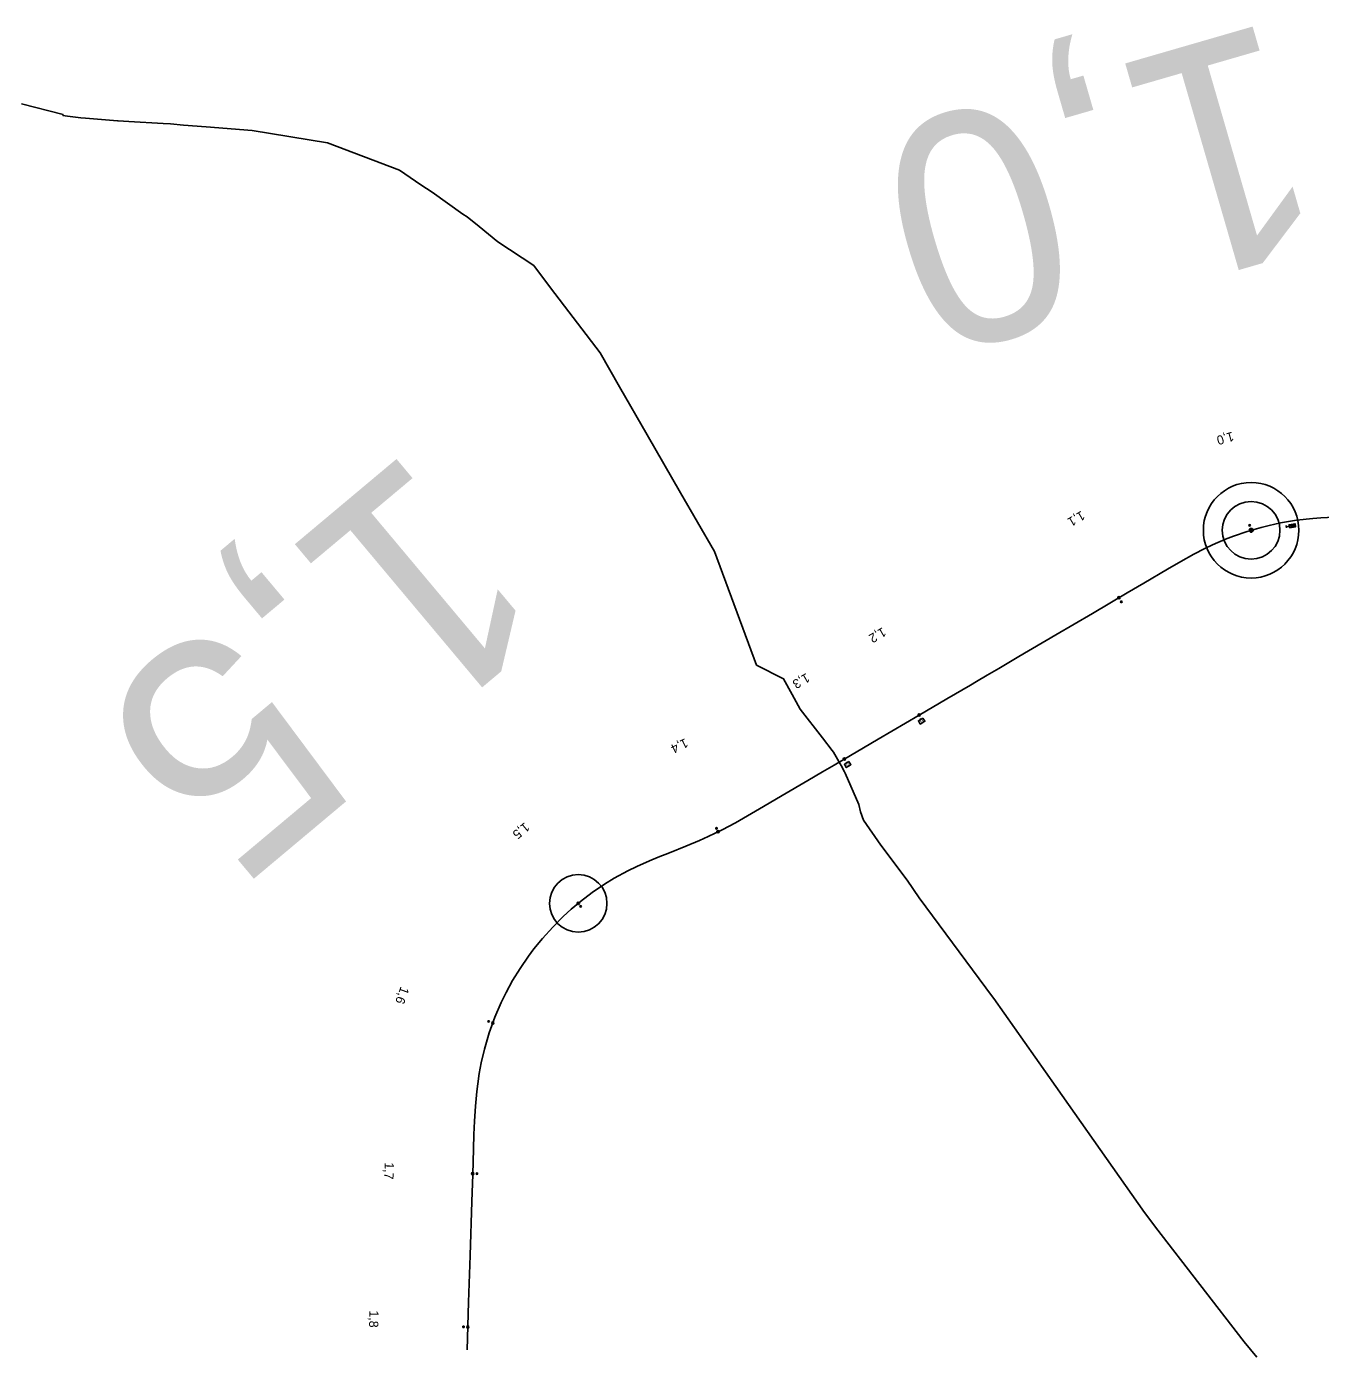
# Model space of a CAD drawing. Extents: x -738519 to -733269, y -1123734 to -1116309.
# Drawn here: x -735766 to -734923, y -1120704 to -1119839 of the extents above; entities that cross this region are included whole.
import ezdxf

# ---------------------------------------------------------------- set-up
doc = ezdxf.new("R2010")
doc.units = 0
for name, color, linetype in [('DKM', 7, 'Continuous'), ('Vrstva 1', 7, 'Continuous'), ('Vrstva 13', 7, 'Continuous'), ('Vrstva 7', 7, 'Continuous')]:
    doc.layers.add(name, color=color, linetype=linetype)

msp = doc.modelspace()

# ---------------------------------------------------------------- linework, layer by layer
at = {"layer": 'DKM'}
msp.add_lwpolyline([(-734964.14, -1120706.24), (-734972.36, -1120696.27), (-735030.04, -1120621.33), (-735033.19, -1120617.24), (-735037.29, -1120611.91), (-735095.05, -1120529.74), (-735135.53, -1120472.38), (-735136.45, -1120471.14), (-735184.26, -1120406.79), (-735192.01, -1120395.09), (-735209.2, -1120372.29), (-735220.41, -1120355.94), (-735222.54, -1120350.71), (-735223.57, -1120345.84), (-735232.39, -1120325.34), (-735232.79, -1120324.54), (-735235.15, -1120320.33), (-735236.32, -1120318.24), (-735237.48, -1120316.17), (-735240.01, -1120311.65), (-735240.86, -1120310.61), (-735247.23, -1120302.41), (-735261.74, -1120283.75), (-735267.06, -1120274.13), (-735272.61, -1120263.87), (-735290.18, -1120254.92), (-735317.57, -1120180.85), (-735339.79, -1120142.5), (-735361.49, -1120104.8), (-735379.62, -1120073.45), (-735392.28, -1120051.31), (-735424.51, -1120008.85), (-735435.47, -1119994.41), (-735458.88, -1119978.9), (-735471.18, -1119968.88), (-735478.93, -1119962.57), (-735481.75, -1119960.82), (-735501.85, -1119946.58), (-735509.06, -1119941.71), (-735523.05, -1119932.09), (-735569.89, -1119914.41), (-735619.21, -1119906.36), (-735649, -1119903.96), (-735663.95, -1119902.76), (-735672.41, -1119902.07), (-735677.05, -1119901.7), (-735699.55, -1119900.4), (-735706.55, -1119900), (-735706.86, -1119899.98), (-735727.79, -1119898.29), (-735730.81, -1119898.05), (-735739.44, -1119896.94), (-735742.5, -1119896.54), (-735742.38, -1119895.95), (-735769.61, -1119889.03)], dxfattribs=at)
at = {"layer": 'Vrstva 1'}
for points in [[(-734858.48, -1120165.34), (-734868.3, -1120163.18), (-734878.26, -1120161.29), (-734888.48, -1120159.82), (-734893.81, -1120159.29), (-734903.72, -1120158.67), (-734913.62, -1120158.56), (-734922.39, -1120158.89), (-734927.49, -1120159.26), (-734938.14, -1120160.47), (-734948.63, -1120162.22), (-734955.93, -1120163.8), (-734961.26, -1120165.13), (-734970.23, -1120167.73), (-734979.17, -1120170.78), (-734984.57, -1120172.85), (-734992.91, -1120176.44), (-734998.02, -1120178.89), (-735005.2, -1120182.65), (-735013.61, -1120187.35), (-735022.2, -1120192.38), (-735037.65, -1120201.44), (-735048.63, -1120207.9)], [(-734858.48, -1120165.34), (-734868.3, -1120163.18), (-734878.26, -1120161.29), (-734888.48, -1120159.82), (-734893.81, -1120159.29), (-734903.72, -1120158.67), (-734913.62, -1120158.56), (-734922.39, -1120158.89), (-734927.49, -1120159.26), (-734938.14, -1120160.47), (-734948.63, -1120162.22), (-734955.93, -1120163.8), (-734961.26, -1120165.13), (-734970.23, -1120167.73), (-734979.17, -1120170.78), (-734984.57, -1120172.85), (-734992.91, -1120176.44), (-734998.02, -1120178.89), (-735005.2, -1120182.65), (-735013.61, -1120187.35), (-735022.2, -1120192.38), (-735037.65, -1120201.44), (-735048.63, -1120207.9)], [(-735048.63, -1120207.9), (-735071.26, -1120221.19), (-735095.02, -1120235.15), (-735119.18, -1120249.35), (-735123.66, -1120251.99), (-735132.32, -1120257.08), (-735139.95, -1120261.55), (-735146.73, -1120265.54), (-735150.83, -1120267.95), (-735166.13, -1120276.92), (-735184.2, -1120287.53), (-735210.89, -1120303.2), (-735238.62, -1120319.49), (-735239.7, -1120320.12), (-735247.26, -1120324.55), (-735256.8, -1120330.14), (-735273.62, -1120340.02), (-735285.77, -1120347.18), (-735296.08, -1120353.22), (-735304.06, -1120357.75)], [(-735048.63, -1120207.9), (-735071.26, -1120221.19), (-735095.02, -1120235.15), (-735119.18, -1120249.35), (-735123.66, -1120251.99), (-735132.32, -1120257.08), (-735139.95, -1120261.55), (-735146.73, -1120265.54), (-735150.83, -1120267.95), (-735166.13, -1120276.92), (-735184.2, -1120287.53), (-735210.89, -1120303.2), (-735238.62, -1120319.49), (-735239.7, -1120320.12), (-735247.26, -1120324.55), (-735256.8, -1120330.14), (-735273.62, -1120340.02), (-735285.77, -1120347.18), (-735296.08, -1120353.22), (-735304.06, -1120357.75)], [(-735304.06, -1120357.75), (-735312.6, -1120362.28), (-735321.76, -1120366.74), (-735327.51, -1120369.32), (-735336.44, -1120373.09), (-735346.98, -1120377.26), (-735354.33, -1120380.21), (-735360.07, -1120382.6), (-735368.33, -1120386.31), (-735374.16, -1120389.16), (-735382.98, -1120393.95), (-735389.27, -1120397.76), (-735397.43, -1120403.28), (-735404.93, -1120408.97), (-735411.01, -1120414.07), (-735416.27, -1120418.85), (-735423.16, -1120425.73), (-735429.79, -1120433.1), (-735435.35, -1120439.92), (-735438.96, -1120444.69), (-735444.43, -1120452.73), (-735449.27, -1120460.68), (-735453.57, -1120468.51), (-735456.72, -1120474.99), (-735460.8, -1120484.48), (-735464.55, -1120494.8), (-735467.61, -1120505.27), (-735469.73, -1120514.19), (-735471.02, -1120521.28), (-735472.03, -1120528.02), (-735472.64, -1120533.02), (-735473.48, -1120542.45), (-735474.08, -1120552.34), (-735474.47, -1120561.09), (-735474.78, -1120570.26), (-735475.33, -1120587.19), (-735475.9, -1120604.74)], [(-735304.06, -1120357.75), (-735312.6, -1120362.28), (-735321.76, -1120366.74), (-735327.51, -1120369.32), (-735336.44, -1120373.09), (-735346.98, -1120377.26), (-735354.33, -1120380.21), (-735360.07, -1120382.6), (-735368.33, -1120386.31), (-735374.16, -1120389.16), (-735382.98, -1120393.95), (-735389.27, -1120397.76), (-735397.43, -1120403.28), (-735404.93, -1120408.97), (-735411.01, -1120414.07), (-735416.27, -1120418.85), (-735423.16, -1120425.73), (-735429.79, -1120433.1), (-735435.35, -1120439.92), (-735438.96, -1120444.69), (-735444.43, -1120452.73), (-735449.27, -1120460.68), (-735453.57, -1120468.51), (-735456.72, -1120474.99), (-735460.8, -1120484.48), (-735464.55, -1120494.8), (-735467.61, -1120505.27), (-735469.73, -1120514.19), (-735471.02, -1120521.28), (-735472.03, -1120528.02), (-735472.64, -1120533.02), (-735473.48, -1120542.45), (-735474.08, -1120552.34), (-735474.47, -1120561.09), (-735474.78, -1120570.26), (-735475.33, -1120587.19), (-735475.9, -1120604.74)], [(-735475.9, -1120604.74), (-735477.02, -1120639.86), (-735477.98, -1120670.26), (-735478.96, -1120701.34)], [(-735475.9, -1120604.74), (-735477.02, -1120639.86), (-735477.98, -1120670.26), (-735478.96, -1120701.34)]]:
    msp.add_lwpolyline(points, dxfattribs=at)
at = {"layer": 'Vrstva 13'}
for p, q in [((-735769.61, -1119889.03), (-735742.38, -1119895.95)), ((-735742.38, -1119895.95), (-735742.5, -1119896.54)), ((-735742.5, -1119896.54), (-735739.44, -1119896.94)), ((-735739.44, -1119896.94), (-735730.81, -1119898.05)), ((-735727.79, -1119898.29), (-735730.81, -1119898.05)), ((-735706.86, -1119899.98), (-735727.79, -1119898.29)), ((-735706.55, -1119900), (-735706.86, -1119899.98)), ((-735699.55, -1119900.4), (-735706.55, -1119900)), ((-735677.05, -1119901.7), (-735699.55, -1119900.4)), ((-735672.41, -1119902.07), (-735677.05, -1119901.7)), ((-735663.95, -1119902.76), (-735672.41, -1119902.07)), ((-735649, -1119903.96), (-735663.95, -1119902.76)), ((-735619.21, -1119906.36), (-735649, -1119903.96)), ((-735569.89, -1119914.41), (-735619.21, -1119906.36)), ((-735523.05, -1119932.09), (-735569.89, -1119914.41)), ((-735523.05, -1119932.09), (-735509.06, -1119941.71)), ((-735509.06, -1119941.71), (-735501.85, -1119946.58)), ((-735501.85, -1119946.58), (-735481.75, -1119960.82)), ((-735481.75, -1119960.82), (-735478.93, -1119962.57)), ((-735478.93, -1119962.57), (-735471.18, -1119968.88)), ((-735471.18, -1119968.88), (-735458.88, -1119978.9)), ((-735435.47, -1119994.41), (-735458.88, -1119978.9)), ((-735424.51, -1120008.85), (-735435.47, -1119994.41)), ((-735392.28, -1120051.31), (-735424.51, -1120008.85)), ((-735379.62, -1120073.45), (-735392.28, -1120051.31)), ((-735379.62, -1120073.45), (-735361.49, -1120104.8)), ((-735361.49, -1120104.8), (-735339.79, -1120142.5)), ((-735339.79, -1120142.5), (-735317.57, -1120180.85)), ((-735317.57, -1120180.85), (-735290.18, -1120254.92)), ((-735290.18, -1120254.92), (-735272.61, -1120263.87)), ((-735272.61, -1120263.87), (-735267.06, -1120274.13)), ((-735267.06, -1120274.13), (-735261.74, -1120283.75)), ((-735261.74, -1120283.75), (-735247.23, -1120302.41)), ((-735247.23, -1120302.41), (-735240.86, -1120310.61)), ((-735240.86, -1120310.61), (-735240.01, -1120311.65)), ((-735240.01, -1120311.65), (-735237.48, -1120316.17)), ((-735237.48, -1120316.17), (-735236.32, -1120318.24)), ((-735236.32, -1120318.24), (-735235.15, -1120320.33)), ((-735235.15, -1120320.33), (-735232.79, -1120324.54)), ((-735232.79, -1120324.54), (-735232.39, -1120325.34)), ((-735232.39, -1120325.34), (-735223.57, -1120345.84)), ((-735223.57, -1120345.84), (-735222.54, -1120350.71)), ((-735222.54, -1120350.71), (-735220.41, -1120355.94)), ((-735220.41, -1120355.94), (-735209.2, -1120372.29)), ((-735209.2, -1120372.29), (-735192.01, -1120395.09)), ((-735192.01, -1120395.09), (-735184.26, -1120406.79)), ((-735184.26, -1120406.79), (-735136.45, -1120471.14)), ((-735136.45, -1120471.14), (-735135.53, -1120472.38)), ((-735135.53, -1120472.38), (-735095.05, -1120529.74)), ((-735095.05, -1120529.74), (-735037.29, -1120611.91)), ((-735037.29, -1120611.91), (-735033.19, -1120617.24)), ((-735033.19, -1120617.24), (-735030.04, -1120621.33)), ((-735030.04, -1120621.33), (-734972.36, -1120696.27)), ((-734972.36, -1120696.27), (-734964.14, -1120706.24))]:
    msp.add_line(p, q, dxfattribs=at)
at = {"layer": 'Vrstva 7'}
for p, q in [((-734968.65, -1120163.77), (-734968.74, -1120163.8)), ((-734968.65, -1120163.77), (-734968.74, -1120163.8)), ((-734944.99, -1120163.95), (-734944.74, -1120165.43)), ((-734944.99, -1120163.95), (-734944.74, -1120165.43)), ((-734942.57, -1120163.29), (-734941.25, -1120165.1)), ((-734942.57, -1120163.29), (-734941.25, -1120165.1)), ((-734940.26, -1120164.93), (-734941.58, -1120163.12)), ((-734940.26, -1120164.93), (-734941.58, -1120163.12)), ((-734940.59, -1120162.96), (-734939.28, -1120164.77)), ((-734940.59, -1120162.96), (-734939.28, -1120164.77)), ((-735052.31, -1120213.67), (-735052.4, -1120213.72)), ((-735052.31, -1120213.67), (-735052.4, -1120213.72)), ((-735183.52, -1120289.79), (-735183.21, -1120290.33)), ((-735183.52, -1120289.79), (-735183.21, -1120290.33)), ((-735231.79, -1120318.14), (-735231.47, -1120318.68)), ((-735231.79, -1120318.14), (-735231.47, -1120318.68)), ((-735316.31, -1120361.39), (-735316.4, -1120361.43)), ((-735316.31, -1120361.39), (-735316.4, -1120361.43)), ((-735404.86, -1120412.19), (-735404.94, -1120412.26)), ((-735404.86, -1120412.19), (-735404.94, -1120412.26)), ((-735464.95, -1120487.25), (-735464.98, -1120487.34)), ((-735464.95, -1120487.25), (-735464.98, -1120487.34)), ((-735472.51, -1120586.52), (-735472.52, -1120586.62)), ((-735472.51, -1120586.52), (-735472.52, -1120586.62)), ((-735481.32, -1120686.38), (-735481.33, -1120686.48)), ((-735481.32, -1120686.38), (-735481.33, -1120686.48))]:
    msp.add_line(p, q, dxfattribs=at)
msp.add_lwpolyline([(-734944.87, -1120164.69), (-734942.9, -1120164.36), (-734942.73, -1120165.34), (-734938.79, -1120164.68), (-734939.12, -1120162.71), (-734943.06, -1120163.37), (-734942.9, -1120164.36)], dxfattribs=at)
msp.add_lwpolyline([(-734944.87, -1120164.69), (-734942.9, -1120164.36), (-734942.73, -1120165.34), (-734938.79, -1120164.68), (-734939.12, -1120162.71), (-734943.06, -1120163.37), (-734942.9, -1120164.36)], dxfattribs=at)
for points in [[(-735181.71, -1120289.44), (-735180.45, -1120291.58), (-735183.46, -1120293.35), (-735184.71, -1120291.21)], [(-735181.71, -1120289.44), (-735180.45, -1120291.58), (-735183.46, -1120293.35), (-735184.71, -1120291.21)], [(-735229.97, -1120317.8), (-735228.71, -1120319.94), (-735231.72, -1120321.71), (-735232.98, -1120319.56)], [(-735229.97, -1120317.8), (-735228.71, -1120319.94), (-735231.72, -1120321.71), (-735232.98, -1120319.56)]]:
    msp.add_lwpolyline(points, close=True, dxfattribs=at)
for centre, radius in [((-734967.76, -1120167.01), 31.14), ((-734967.76, -1120167.01), 18.8), ((-734968.7, -1120163.79), 0.5), ((-734968.7, -1120163.79), 0.5), ((-734967.76, -1120167.01), 1.25), ((-734967.76, -1120167.01), 0.752), ((-735053.94, -1120211.01), 0.75), ((-735053.94, -1120211.01), 0.75), ((-735052.36, -1120213.7), 0.5), ((-735052.36, -1120213.7), 0.5), ((-735184.2, -1120287.53), 0.75), ((-735184.2, -1120287.53), 0.75), ((-735232.95, -1120316.16), 0.75), ((-735232.95, -1120316.16), 0.75), ((-735316.35, -1120361.41), 0.5), ((-735316.35, -1120361.41), 0.5), ((-735315.29, -1120363.59), 0.75), ((-735315.29, -1120363.59), 0.75), ((-735406.51, -1120410.3), 18.75), ((-735406.51, -1120410.3), 0.75), ((-735404.9, -1120412.22), 0.5), ((-735404.9, -1120412.22), 0.5), ((-735464.97, -1120487.29), 0.5), ((-735464.97, -1120487.29), 0.5), ((-735462.19, -1120488.3), 0.75), ((-735462.19, -1120488.3), 0.75), ((-735475.31, -1120586.48), 0.75), ((-735475.31, -1120586.48), 0.75), ((-735472.51, -1120586.57), 0.5), ((-735472.51, -1120586.57), 0.5), ((-735481.32, -1120686.43), 0.5), ((-735481.32, -1120686.43), 0.5), ((-735478.49, -1120686.52), 0.75), ((-735478.49, -1120686.52), 0.75)]:
    msp.add_circle(centre, radius, dxfattribs=at)

# ---------------------------------------------------------------- texts
for s, height, rotation, p in [('1,0', 150, 196.1569, (-734952.1, -1119834.29)), ('1,0', 6, 196.1569, (-734980.05, -1120102.69)), ('1,5', 150, 219.97011, (-735513.29, -1120110.72)), ('1,1', 6, 210.43998, (-735078.4, -1120154.11)), ('1,1', 6, 210.43998, (-735078.4, -1120154.11)), ('1,2', 6, 210.41497, (-735207.99, -1120230.05)), ('1,2', 6, 210.41497, (-735207.99, -1120230.05)), ('1,3', 6, 210.42534, (-735257.8, -1120259.91)), ('1,3', 6, 210.42534, (-735257.8, -1120259.91)), ('KM', 1.247, 210.41497, (-735182.02, -1120290.34)), ('KM', 1.247, 210.41497, (-735182.02, -1120290.34)), ('1,4', 6, 205.94612, (-735336.73, -1120302.46)), ('1,4', 6, 205.94612, (-735336.73, -1120302.46)), ('KM', 1.247, 210.42534, (-735230.28, -1120318.7)), ('KM', 1.247, 210.42534, (-735230.28, -1120318.7)), ('1,5', 6, 219.97011, (-735441.35, -1120357.12)), ('1,6', 6, 250.06595, (-735522.15, -1120464.09)), ('1,6', 6, 250.06595, (-735522.15, -1120464.09)), ('1,7', 6, 268.13309, (-735532.65, -1120579.1)), ('1,7', 6, 268.13309, (-735532.65, -1120579.1)), ('1,8', 6, 268.19927, (-735542.59, -1120675.68)), ('1,8', 6, 268.19927, (-735542.59, -1120675.68))]:
    msp.add_text(s, height=height, rotation=rotation, dxfattribs=at).set_placement(p)

doc.saveas('drawing.dxf')
